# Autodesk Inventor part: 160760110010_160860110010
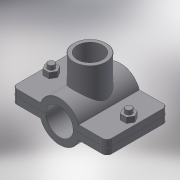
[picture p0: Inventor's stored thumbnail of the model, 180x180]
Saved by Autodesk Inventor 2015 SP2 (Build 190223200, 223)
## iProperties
Created: 2017-05
Part Number: 160760110010_160860110010
Material: Generic
Description: PLASSON SADDLE 110-1"
Document SubType Name: Modeling
Designer: KIM
Density: 1 g/cm^3
Appearance: Default
Author: KIM
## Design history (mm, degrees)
derived "16076.ipt"
feature "Solid1::16076.ipt"
feature "Solid2::16076.ipt"
tag "TaggingFeature1"
body "Solid1"
other parameters: "d0" = 121, "d1" = 165, "d2" = 55, "d4" = 116, "d5" = 0, "d6" = 8.25, "d7" = 165, "d8" = 0.1, "d10" = 0, "d11" = 1.1, "d14" = 39.3783, "d20" = 1.1, "d23" = 1.1, "d36" = 13, "d37" = 10.4, "d38" = 63, "d39" = 0, "d40" = 3, "d41" = 5, "d42" = 0, "d43" = 8, "d44" = 3, "d45" = 0, "d46" = 1.1, "d51" = 87, "d52" = 30.291, "d53" = 21, "d54" = 0, "d55" = 25, "d57" = 0, "d58" = 118.8, "d60" = 0, "d62" = 13, "d63" = 10.4, "d66" = 95.2, "B_" = 25, "G_" = 30.291, "A_" = 87, "L_" = 165, "L_1" = 116, "l_2" = 21
